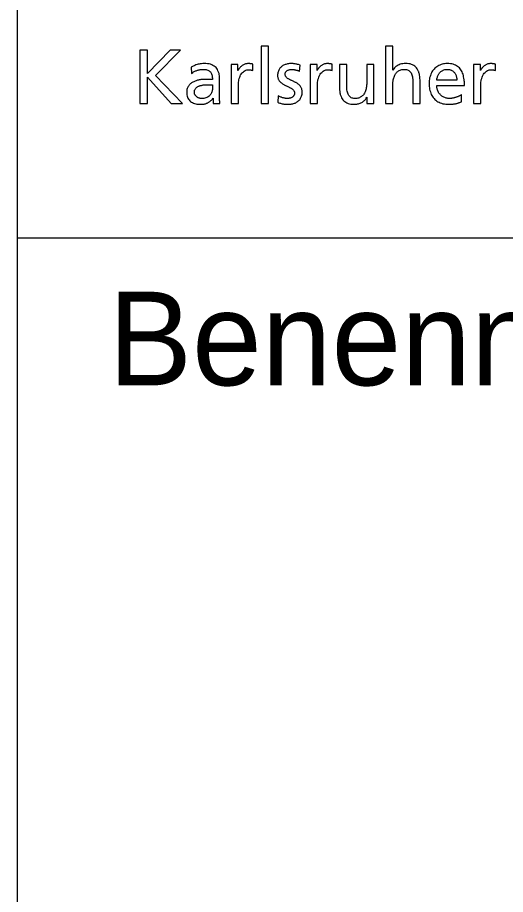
# Model space of a CAD drawing. Extents: x 0 to 84, y 0 to 59.4.
# Drawn here: x 65.6 to 67.682, y 8.949 to 12.693 of the extents above; entities that cross this region are included whole.
import ezdxf

# ---------------------------------------------------------------- set-up
doc = ezdxf.new("R2010")
doc.units = 0
doc.layers.add('90_Plankopf', color=7, linetype='Continuous')

msp = doc.modelspace()

# ---------------------------------------------------------------- linework, layer by layer
at = {"layer": '90_Plankopf'}
for p, q in [((66.1226, 12.5532), (66.1226, 12.3263)), ((66.3408, 12.4804), (66.3424, 12.4544)), ((66.6045, 12.4664), (66.6045, 12.4937)), ((66.8038, 12.4628), (66.8064, 12.4895)), ((66.942, 12.4664), (66.942, 12.4937)), ((67.6388, 12.4664), (67.6388, 12.4937)), ((66.4315, 12.4053), (66.4315, 12.3907)), ((66.462, 12.3588), (66.462, 12.4274)), ((67.4746, 12.4251), (67.3887, 12.4251)), ((67.3887, 12.4024), (67.5071, 12.4024)), ((66.7124, 12.3588), (66.7108, 12.3315)), ((67.4944, 12.3331), (67.4944, 12.3637)), ((66.1226, 12.3263), (66.1551, 12.3263)), ((66.2562, 12.3263), (66.3037, 12.3263)), ((65.6002, 11.752), (82.4, 11.752))]:
    msp.add_line(p, q, dxfattribs=at)
for points in [[(65.6002, 4.138), (65.6002, 15.136)], [(66.3037, 12.3263), (66.1886, 12.4459), (66.2952, 12.5532), (66.252, 12.5532), (66.1551, 12.4534), (66.1551, 12.5532), (66.1226, 12.5532)], [(66.6402, 12.3263), (66.6708, 12.3263), (66.6708, 12.5701), (66.6402, 12.5701), (66.6402, 12.3263)], [(67.2018, 12.4683), (67.2011, 12.4683), (67.2011, 12.5701), (67.1706, 12.5701), (67.1706, 12.3263), (67.2011, 12.3263), (67.2011, 12.403)], [(66.5411, 12.4664), (66.5404, 12.4664), (66.5404, 12.4921), (66.5118, 12.4921), (66.5118, 12.3263), (66.5424, 12.3263), (66.5424, 12.4017)], [(66.8786, 12.4664), (66.8779, 12.4664), (66.8779, 12.4921), (66.8493, 12.4921), (66.8493, 12.3263), (66.8799, 12.3263), (66.8799, 12.4017)], [(67.0044, 12.4063), (67.0044, 12.4921), (66.9739, 12.4921), (66.9739, 12.3936)], [(67.0902, 12.3526), (67.0909, 12.3526), (67.0909, 12.3263), (67.1205, 12.3263), (67.1205, 12.4921), (67.0899, 12.4921), (67.0899, 12.4154)], [(67.5754, 12.4664), (67.5747, 12.4664), (67.5747, 12.4921), (67.5461, 12.4921), (67.5461, 12.3263), (67.5767, 12.3263), (67.5767, 12.4017)], [(66.1551, 12.3263), (66.1551, 12.4375), (66.2562, 12.3263)], [(67.2866, 12.4121), (67.2866, 12.3263), (67.3172, 12.3263), (67.3172, 12.4248)], [(66.4341, 12.3478), (66.4347, 12.3478), (66.4347, 12.3263), (66.4633, 12.3263)]]:
    msp.add_lwpolyline(points, dxfattribs=at)
for points in [[(66.462, 12.4274), (66.4621, 12.4424), (66.4599, 12.4551), (66.4553, 12.4652), (66.4508, 12.4754), (66.4436, 12.4831), (66.4337, 12.4882), (66.4239, 12.4934), (66.4112, 12.496), (66.3954, 12.496), (66.3848, 12.4959), (66.375, 12.4945), (66.3659, 12.4916), (66.3568, 12.4888), (66.3484, 12.485), (66.3408, 12.4804)], [(66.3424, 12.4544), (66.3466, 12.4578), (66.3513, 12.4609), (66.3565, 12.4634), (66.3618, 12.4659), (66.3673, 12.4679), (66.3731, 12.4692), (66.3789, 12.4706), (66.3847, 12.4713), (66.3905, 12.4713), (66.4007, 12.4713), (66.4087, 12.4696), (66.4147, 12.4665), (66.4208, 12.4632), (66.425, 12.4584), (66.4276, 12.452), (66.4303, 12.4455), (66.4315, 12.4376), (66.4315, 12.428)], [(66.6045, 12.4937), (66.6023, 12.4941), (66.6003, 12.4945), (66.5984, 12.4949), (66.5964, 12.4952), (66.5943, 12.4955), (66.5921, 12.4957), (66.5899, 12.4959), (66.5873, 12.496), (66.5843, 12.496), (66.5784, 12.4959), (66.5727, 12.4947), (66.5671, 12.4921), (66.5615, 12.4896), (66.5565, 12.4862), (66.552, 12.4817), (66.5475, 12.4773), (66.5438, 12.4722), (66.5411, 12.4664)], [(66.5424, 12.4017), (66.5424, 12.4156), (66.5443, 12.4276), (66.548, 12.4377), (66.5517, 12.4478), (66.5569, 12.4556), (66.5637, 12.461), (66.5704, 12.4665), (66.5784, 12.4693), (66.5875, 12.4693), (66.5902, 12.4694), (66.593, 12.4692), (66.5959, 12.4687), (66.5988, 12.4683), (66.6016, 12.4675), (66.6045, 12.4664)], [(66.8064, 12.4895), (66.8004, 12.4913), (66.7944, 12.4928), (66.7882, 12.4941), (66.7821, 12.4953), (66.7755, 12.4959), (66.7684, 12.496), (66.7601, 12.496), (66.7524, 12.4949), (66.7454, 12.4928), (66.7383, 12.4908), (66.7321, 12.4876), (66.7268, 12.4834), (66.7215, 12.4792), (66.7173, 12.4739), (66.7144, 12.4675), (66.7114, 12.4611), (66.7099, 12.4535), (66.7098, 12.4449), (66.7099, 12.4383), (66.7113, 12.4326), (66.7139, 12.4278), (66.7164, 12.4229), (66.7198, 12.4188), (66.7241, 12.4152), (66.7284, 12.4117), (66.733, 12.4085), (66.7381, 12.4058), (66.7432, 12.403), (66.7483, 12.4005), (66.7534, 12.3981), (66.7585, 12.3956), (66.7632, 12.3932), (66.7674, 12.3906), (66.7717, 12.3881), (66.7751, 12.3852), (66.7777, 12.382), (66.7803, 12.3788), (66.7816, 12.3751), (66.7817, 12.3708), (66.7816, 12.3664), (66.7807, 12.3626), (66.7788, 12.3596), (66.7769, 12.3565), (66.7744, 12.3541), (66.7713, 12.3523), (66.7683, 12.3504), (66.7649, 12.3491), (66.7613, 12.3483), (66.7576, 12.3475), (66.754, 12.3471), (66.7505, 12.3471), (66.7475, 12.3471), (66.7438, 12.3475), (66.7394, 12.3484), (66.735, 12.3493), (66.7304, 12.3505), (66.7257, 12.3523), (66.721, 12.354), (66.7166, 12.3562), (66.7124, 12.3588)], [(66.7108, 12.3315), (66.7179, 12.3279), (66.7252, 12.3254), (66.733, 12.3241), (66.7407, 12.3229), (66.7485, 12.3223), (66.7563, 12.3224), (66.7638, 12.3224), (66.771, 12.3234), (66.7778, 12.3255), (66.7847, 12.3275), (66.7909, 12.3307), (66.7964, 12.335), (66.8018, 12.3392), (66.8061, 12.3445), (66.8093, 12.3511), (66.8125, 12.3575), (66.8141, 12.3652), (66.8142, 12.3741), (66.8141, 12.3816), (66.8128, 12.388), (66.8102, 12.3933), (66.8076, 12.3985), (66.8042, 12.403), (66.7999, 12.4066), (66.7957, 12.4103), (66.791, 12.4134), (66.7859, 12.416), (66.7808, 12.4186), (66.7757, 12.421), (66.7706, 12.4233), (66.7655, 12.4256), (66.7608, 12.4279), (66.7566, 12.4303), (66.7523, 12.4328), (66.7489, 12.4357), (66.7463, 12.439), (66.7438, 12.4423), (66.7424, 12.4463), (66.7424, 12.4511), (66.7424, 12.4557), (66.7438, 12.4595), (66.7465, 12.4624), (66.7491, 12.4654), (66.7527, 12.4676), (66.7571, 12.4691), (66.7615, 12.4706), (66.7664, 12.4713), (66.7716, 12.4713), (66.7735, 12.4713), (66.7758, 12.471), (66.7787, 12.4706), (66.7816, 12.4701), (66.7846, 12.4694), (66.7878, 12.4686), (66.7911, 12.4679), (66.794, 12.4669), (66.7969, 12.4659), (66.7997, 12.4649), (66.802, 12.4639), (66.8038, 12.4628)], [(66.942, 12.4937), (66.9399, 12.4941), (66.9378, 12.4945), (66.9359, 12.4949), (66.934, 12.4952), (66.9318, 12.4955), (66.9296, 12.4957), (66.9274, 12.4959), (66.9248, 12.496), (66.9218, 12.496), (66.9159, 12.4959), (66.9102, 12.4947), (66.9046, 12.4921), (66.8991, 12.4896), (66.894, 12.4862), (66.8895, 12.4817), (66.885, 12.4773), (66.8814, 12.4722), (66.8786, 12.4664)], [(66.8799, 12.4017), (66.88, 12.4156), (66.8818, 12.4276), (66.8855, 12.4377), (66.8893, 12.4478), (66.8945, 12.4556), (66.9012, 12.461), (66.908, 12.4665), (66.9159, 12.4693), (66.9251, 12.4693), (66.9277, 12.4694), (66.9305, 12.4692), (66.9334, 12.4687), (66.9363, 12.4683), (66.9392, 12.4675), (66.942, 12.4664)], [(67.2011, 12.403), (67.2011, 12.4131), (67.2021, 12.4224), (67.2041, 12.4307), (67.2061, 12.439), (67.2092, 12.4462), (67.2133, 12.4522), (67.2174, 12.4583), (67.2226, 12.463), (67.229, 12.4663), (67.2353, 12.4696), (67.2429, 12.4712), (67.2515, 12.4713), (67.2604, 12.4707), (67.2673, 12.4683), (67.2725, 12.4638), (67.2776, 12.4594), (67.2813, 12.4528), (67.2834, 12.4443), (67.2857, 12.4357), (67.2867, 12.425), (67.2866, 12.4121)], [(67.3172, 12.4248), (67.3172, 12.4397), (67.315, 12.4524), (67.3106, 12.463), (67.3062, 12.4737), (67.2994, 12.4818), (67.2903, 12.4874), (67.2811, 12.4931), (67.2694, 12.4959), (67.2551, 12.496), (67.2434, 12.4959), (67.2331, 12.4935), (67.2239, 12.4888), (67.2148, 12.484), (67.2074, 12.4772), (67.2018, 12.4683)], [(67.5071, 12.4024), (67.5071, 12.4157), (67.5059, 12.4282), (67.5034, 12.4395), (67.501, 12.4508), (67.4969, 12.4607), (67.4913, 12.4692), (67.4856, 12.4776), (67.4781, 12.4842), (67.4687, 12.4888), (67.4593, 12.4935), (67.4477, 12.4959), (67.4339, 12.496), (67.4222, 12.4959), (67.4116, 12.4938), (67.402, 12.4898), (67.3925, 12.4857), (67.3844, 12.4799), (67.3775, 12.4725), (67.3707, 12.465), (67.3654, 12.4562), (67.3618, 12.4459), (67.3581, 12.4357), (67.3563, 12.4245), (67.3562, 12.4121), (67.3562, 12.3986), (67.3579, 12.3863), (67.3614, 12.3753), (67.3648, 12.3643), (67.3701, 12.3549), (67.3771, 12.347), (67.3841, 12.3391), (67.393, 12.333), (67.4038, 12.3288), (67.4146, 12.3246), (67.4274, 12.3224), (67.4421, 12.3224), (67.4511, 12.3224), (67.4588, 12.3231), (67.4652, 12.3242), (67.4715, 12.3254), (67.4771, 12.3268), (67.4817, 12.3284), (67.4863, 12.3301), (67.4906, 12.3317), (67.4944, 12.3331)], [(67.3887, 12.4251), (67.3893, 12.4305), (67.3905, 12.4359), (67.3925, 12.4414), (67.3944, 12.4468), (67.3971, 12.4517), (67.4007, 12.4563), (67.4042, 12.4608), (67.4086, 12.4643), (67.414, 12.4671), (67.4194, 12.4698), (67.4258, 12.4712), (67.4333, 12.4713), (67.4399, 12.4712), (67.4457, 12.47), (67.4508, 12.4676), (67.456, 12.4652), (67.4603, 12.462), (67.4638, 12.4577), (67.4673, 12.4535), (67.47, 12.4486), (67.4718, 12.4431), (67.4736, 12.4375), (67.4746, 12.4315), (67.4746, 12.4251)], [(67.6388, 12.4937), (67.6367, 12.4941), (67.6346, 12.4945), (67.6327, 12.4949), (67.6308, 12.4952), (67.6286, 12.4955), (67.6264, 12.4957), (67.6242, 12.4959), (67.6216, 12.496), (67.6186, 12.496), (67.6127, 12.4959), (67.607, 12.4947), (67.6014, 12.4921), (67.5959, 12.4896), (67.5908, 12.4862), (67.5863, 12.4817), (67.5818, 12.4773), (67.5781, 12.4722), (67.5754, 12.4664)], [(67.5767, 12.4017), (67.5767, 12.4156), (67.5786, 12.4276), (67.5823, 12.4377), (67.586, 12.4478), (67.5912, 12.4556), (67.598, 12.461), (67.6047, 12.4665), (67.6127, 12.4693), (67.6219, 12.4693), (67.6245, 12.4694), (67.6273, 12.4692), (67.6302, 12.4687), (67.6331, 12.4683), (67.6359, 12.4675), (67.6388, 12.4664)], [(66.4315, 12.428), (66.4275, 12.4283), (66.4238, 12.4284), (66.4204, 12.4285), (66.4169, 12.4286), (66.4135, 12.4286), (66.4101, 12.4287), (66.4067, 12.4287), (66.4029, 12.4287), (66.399, 12.4287), (66.3926, 12.4287), (66.3859, 12.4282), (66.3789, 12.427), (66.3718, 12.4259), (66.3649, 12.424), (66.3582, 12.4214), (66.3515, 12.4189), (66.3454, 12.4155), (66.34, 12.4113), (66.3345, 12.4071), (66.3302, 12.4019), (66.3269, 12.3957), (66.3237, 12.3896), (66.322, 12.3824), (66.3219, 12.3741), (66.322, 12.3621), (66.3246, 12.3523), (66.3297, 12.3446), (66.3349, 12.337), (66.342, 12.3314), (66.3511, 12.3278), (66.3602, 12.3242), (66.3707, 12.3224), (66.3827, 12.3224), (66.3897, 12.3224), (66.396, 12.3233), (66.4015, 12.3249), (66.4071, 12.3266), (66.412, 12.3287), (66.4162, 12.3313), (66.4204, 12.3339), (66.424, 12.3366), (66.427, 12.3395), (66.4299, 12.3424), (66.4323, 12.3451), (66.4341, 12.3478)], [(66.4315, 12.3907), (66.4315, 12.3824), (66.4297, 12.3749), (66.4262, 12.3684), (66.4228, 12.3618), (66.4176, 12.3567), (66.4107, 12.3529), (66.4039, 12.3491), (66.3954, 12.3471), (66.3853, 12.3471), (66.3818, 12.3471), (66.3782, 12.3477), (66.3746, 12.3488), (66.371, 12.35), (66.3677, 12.3517), (66.3646, 12.354), (66.3616, 12.3563), (66.3592, 12.3591), (66.3573, 12.3624), (66.3555, 12.3658), (66.3545, 12.3697), (66.3544, 12.3741), (66.3545, 12.3799), (66.356, 12.3848), (66.3588, 12.3886), (66.3616, 12.3925), (66.3654, 12.3956), (66.3699, 12.3979), (66.3745, 12.4003), (66.3794, 12.402), (66.3846, 12.4032), (66.3898, 12.4043), (66.3948, 12.4051), (66.3996, 12.4054), (66.4044, 12.4058), (66.4086, 12.406), (66.412, 12.4059), (66.4152, 12.4059), (66.4185, 12.4058), (66.4217, 12.4056), (66.425, 12.4054), (66.4282, 12.4053), (66.4315, 12.4053)], [(66.9739, 12.3936), (66.9739, 12.3787), (66.976, 12.3659), (66.9804, 12.3553), (66.9848, 12.3447), (66.9916, 12.3366), (67.0008, 12.3309), (67.01, 12.3253), (67.0217, 12.3224), (67.036, 12.3224), (67.0437, 12.3224), (67.0512, 12.3236), (67.0583, 12.326), (67.0654, 12.3284), (67.0717, 12.3319), (67.0773, 12.3364), (67.0828, 12.3409), (67.0872, 12.3463), (67.0902, 12.3526)], [(67.0899, 12.4154), (67.0899, 12.4052), (67.089, 12.396), (67.0869, 12.3877), (67.0849, 12.3793), (67.0819, 12.3722), (67.0778, 12.3661), (67.0737, 12.36), (67.0684, 12.3554), (67.0621, 12.3521), (67.0557, 12.3488), (67.0482, 12.3471), (67.0395, 12.3471), (67.0307, 12.3476), (67.0237, 12.3501), (67.0186, 12.3546), (67.0134, 12.359), (67.0098, 12.3655), (67.0076, 12.3741), (67.0054, 12.3826), (67.0044, 12.3934), (67.0044, 12.4063)], [(67.4944, 12.3637), (67.4925, 12.3621), (67.4897, 12.3604), (67.4861, 12.3585), (67.4825, 12.3566), (67.4784, 12.3548), (67.4736, 12.353), (67.4689, 12.3513), (67.464, 12.3499), (67.4588, 12.3488), (67.4536, 12.3477), (67.4485, 12.3471), (67.4434, 12.3471), (67.436, 12.3471), (67.4292, 12.3484), (67.4226, 12.3511), (67.4161, 12.3538), (67.4102, 12.3575), (67.4052, 12.3624), (67.4001, 12.3673), (67.3961, 12.3731), (67.3932, 12.3799), (67.3903, 12.3866), (67.3888, 12.3941), (67.3887, 12.4024)], [(66.4633, 12.3263), (66.4631, 12.3279), (66.4629, 12.33), (66.4627, 12.3327), (66.4625, 12.3354), (66.4624, 12.3388), (66.4623, 12.3431), (66.4621, 12.3473), (66.462, 12.3526), (66.462, 12.3588)]]:
    msp.add_open_spline(points, degree=3, dxfattribs=at)

# ---------------------------------------------------------------- texts
msp.add_text('Benennung :', height=0.4, dxfattribs=at).set_placement((65.988, 11.1226))

doc.saveas('drawing.dxf')
